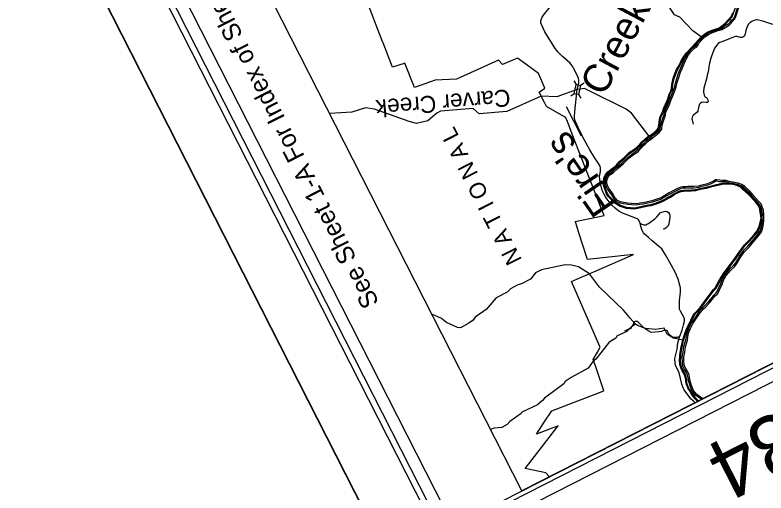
# Model space of a CAD drawing. Extents: x 558484 to 564063, y 513718 to 518374.
# Drawn here: x 559153.7 to 559464.9, y 514651.4 to 514849.4 of the extents above; entities that cross this region are included whole.
import ezdxf

# ---------------------------------------------------------------- set-up
doc = ezdxf.new("R2010")
doc.units = 0
for name, color, linetype in [('Default', 7, 'Continuous'), ('Scratch_Level_3', 7, 'Continuous'), ('Sheet Cutting Line CELL', 7, 'Continuous'), ('Sheet Plot Border Inside CELL', 7, 'Continuous'), ('Sheet Plot Border Outside CELL', 7, 'Continuous'), ('Sheet Title CELL', 7, 'Continuous')]:
    doc.layers.add(name, color=color, linetype=linetype)

msp = doc.modelspace()

# ---------------------------------------------------------------- linework, layer by layer
at = {"layer": 'Default'}
for p, q in [((559385.31, 514822.07), (559386.27, 514820.59)), ((559389.52, 514821.17), (559388.04, 514820.21)), ((559385.49, 514816.8), (559384.01, 514815.83)), ((559387.22, 514816.43), (559388.18, 514814.94)), ((559388.46, 514799.17), (559382.26, 514811.36))]:
    msp.add_line(p, q, dxfattribs=at)
for points in [[(559363.74, 514652.18), (559165.18, 515042.19), (559493.11, 515209.15), (559691.68, 514819.14)], [(559363.74, 514652.18), (559165.18, 515042.19), (559493.11, 515209.15), (559691.68, 514819.14)], [(559388.04, 514820.21), (559387.23, 514816.42), (559385.46, 514816.8), (559386.27, 514820.59)]]:
    msp.add_lwpolyline(points, close=True, dxfattribs=at)
for points in [[(559438.04, 514840.42), (559434.6, 514842.86), (559429.22, 514848.57), (559426.93, 514849.54), (559424.22, 514853.6), (559420.44, 514853.19), (559418.74, 514853.42), (559413.82, 514853.95), (559411.59, 514857.68), (559408.83, 514859.59), (559405, 514861.93), (559403.35, 514863.12), (559402.06, 514865.88), (559401.2, 514868.14), (559400.51, 514869.94), (559399.78, 514872.78), (559399.14, 514873.55), (559398.35, 514873.79)], [(559451.1, 514846.95), (559451.84, 514847.68), (559452.31, 514848.44), (559452.95, 514850.51), (559453.48, 514852.3), (559453.83, 514854.3), (559454.33, 514855.2), (559454.71, 514857.19), (559455.02, 514858.28), (559455.72, 514859.28), (559456.81, 514860.08), (559458.61, 514860.74), (559459.49, 514860.8), (559460.86, 514861.37), (559463.2, 514862.23), (559464.58, 514863), (559465.98, 514863.72)], [(559375.24, 514658.04), (559373.64, 514659.77), (559365.12, 514661.5), (559366.59, 514663.4), (559378.81, 514679.13), (559369.79, 514675.7), (559373.06, 514680.64), (559376.23, 514685.44), (559377.93, 514686.09), (559397.75, 514693.63), (559394.35, 514703.64), (559393.35, 514706.61), (559395.04, 514709.67), (559396.19, 514711.74), (559396.03, 514712.1), (559384.27, 514738.97), (559389.31, 514741.15), (559390.11, 514741.5), (559392.93, 514742.72), (559393.58, 514743), (559410.05, 514750.13), (559390.95, 514748.16), (559390.92, 514748.16), (559387.28, 514759.52), (559386.52, 514761.87), (559386.07, 514763.3), (559385.89, 514763.86), (559391.87, 514765.06), (559397.88, 514766.27), (559396.66, 514769.37), (559384.65, 514800), (559382.61, 514805.22), (559381.97, 514806.86), (559381.11, 514807.36), (559373.89, 514811.55), (559373.12, 514813.11), (559370.96, 514817.42), (559373.22, 514819.07), (559371.55, 514823.02), (559370.66, 514825.14), (559365.37, 514829.01), (559361.91, 514831.54), (559355.7, 514828.93), (559354.08, 514830.68), (559342.4, 514825.46), (559336.63, 514822.88), (559327.78, 514822.41), (559319.25, 514819.31), (559315.29, 514829.44), (559314.98, 514829.34), (559310.11, 514827.77), (559306.25, 514837.85), (559306.18, 514838.03), (559298.85, 514857.17)], [(559438.33, 514840.14), (559439.81, 514841.31), (559440.98, 514842.11), (559443.09, 514842.96), (559445.67, 514843.83), (559446.87, 514844.66), (559448.27, 514845.79), (559449.57, 514847.14), (559450.87, 514848.67), (559451.5, 514850.13), (559452.25, 514852.5), (559452.8, 514854.03), (559453.04, 514855.01), (559453.11, 514855.8), (559453.15, 514855.94)], [(559386.72, 514818.5), (559386.82, 514819.3), (559387.3, 514821.28), (559387.31, 514822.37), (559387.18, 514823.15), (559386.88, 514823.98), (559385.17, 514827.35), (559384.56, 514828.37), (559383.71, 514829.47), (559382.69, 514830.48), (559380.55, 514832.25), (559378.78, 514834), (559378.19, 514834.7), (559377.57, 514835.56), (559376.66, 514836.97), (559374.32, 514840.59), (559373.29, 514842.45), (559372.55, 514844.02), (559371.84, 514845.43), (559371.66, 514846.19), (559371.66, 514847.03), (559371.87, 514847.88), (559372.18, 514848.5), (559372.71, 514849.31), (559375.62, 514852.89)], [(559450.62, 514847.29), (559451.52, 514847.94), (559451.93, 514848.62), (559452.56, 514850.63), (559453.07, 514852.39), (559453.43, 514854.44), (559453.72, 514854.86)], [(559438.04, 514840.42), (559439.6, 514841.6), (559440.81, 514842.43), (559442.96, 514843.3), (559445.51, 514844.16), (559446.65, 514844.95), (559448.03, 514846.05), (559449.3, 514847.38), (559450.56, 514848.87), (559451.16, 514850.26)], [(559425.7, 514816.19), (559426.74, 514818.62), (559427.08, 514819.85), (559427.4, 514821.23), (559428.44, 514824.49), (559428.96, 514826), (559429.63, 514827.52), (559431.16, 514831.1), (559432.36, 514833.21), (559433.31, 514834.56), (559434.96, 514836.2), (559435.72, 514836.61), (559436.12, 514837.06), (559436.74, 514838.23), (559437.99, 514839.41), (559439.32, 514840.58), (559440.81, 514841.83), (559442.15, 514842.46), (559444.52, 514843.15), (559446.41, 514843.71), (559447.89, 514844.88), (559449.35, 514845.75), (559450.04, 514846.46), (559450.62, 514847.29)], [(559426.25, 514815.97), (559427.29, 514818.42), (559427.65, 514819.71), (559427.97, 514821.07), (559429, 514824.3), (559429.51, 514825.79), (559430.18, 514827.29), (559431.69, 514830.84), (559432.86, 514832.89), (559433.76, 514834.18), (559435.31, 514835.72), (559436.09, 514836.14), (559436.6, 514836.73), (559437.23, 514837.89), (559438.34, 514839.12), (559439.58, 514840.31), (559441.12, 514841.33), (559442.46, 514842.08), (559444.74, 514842.82), (559446.64, 514843.38), (559448.2, 514844.37), (559449.72, 514845.28), (559450.5, 514846.08), (559451.1, 514846.95)], [(559467.7, 514845.52), (559463.53, 514846.91), (559461.25, 514847.46), (559460.92, 514847.45), (559459.88, 514847.16), (559458.97, 514846.77), (559458.28, 514846.29), (559457.57, 514845.48), (559456.92, 514844.29), (559456.56, 514843.05), (559456.28, 514841.58), (559455.96, 514840.81), (559455.72, 514840.5), (559455.27, 514840.2), (559454.84, 514840.07), (559454.4, 514840.09), (559452.85, 514840.51), (559452.28, 514840.54), (559451.42, 514840.23), (559449.75, 514839.55), (559447.29, 514838.6), (559445.82, 514837.99), (559445.14, 514837.54), (559444.46, 514836.84), (559443.77, 514835.83), (559442.87, 514833.94), (559442.05, 514831.58), (559441.4, 514828.97), (559441.02, 514826.76), (559440.93, 514825.81), (559440.6, 514824.48), (559440.34, 514823.58), (559439.18, 514819.1), (559438.98, 514817.89), (559438.98, 514817.41), (559439.34, 514816.17), (559439.43, 514815.9), (559439.62, 514815.65), (559440.41, 514815.05), (559440.87, 514814.24), (559440.98, 514813.73), (559440.86, 514813.35), (559440.61, 514813.11), (559440.17, 514813.12), (559438.88, 514813.3), (559438.18, 514813.15), (559437.7, 514812.85), (559437.32, 514812.47), (559436.89, 514811.09), (559436.75, 514810.36), (559436.69, 514809.87), (559436.6, 514809.54), (559436.39, 514809.22), (559434.9, 514807.93), (559434.51, 514807.54), (559434.28, 514806.93), (559434.22, 514806.46), (559434.29, 514806.04), (559434.74, 514804.14)], [(559416.42, 514799.32), (559417.14, 514799.83), (559418.55, 514800.74), (559419.84, 514802.02), (559420.22, 514802.54), (559420.32, 514803.1), (559420.66, 514804.94), (559420.8, 514806.24), (559421.12, 514807.32), (559421.83, 514808.87), (559422.62, 514810.99), (559423.27, 514812.48), (559424.27, 514814.69), (559424.75, 514816.56), (559425.42, 514818.02), (559425.71, 514818.91), (559425.93, 514820.62), (559426.51, 514823.24), (559427, 514824.77), (559427.88, 514826.82), (559429.01, 514828.76), (559429.66, 514830.18), (559430.87, 514832.16), (559431.89, 514833.58), (559434.2, 514836.1), (559435.49, 514837.67), (559436.76, 514839.05), (559438.04, 514840.42)], [(559416.67, 514799.01), (559417.37, 514799.5), (559418.8, 514800.43), (559420.15, 514801.76), (559420.6, 514802.38), (559420.71, 514803.03), (559421.05, 514804.88), (559421.2, 514806.16), (559421.5, 514807.18), (559422.2, 514808.71), (559423, 514810.84), (559423.64, 514812.31), (559424.65, 514814.55), (559425.13, 514816.43), (559425.79, 514817.88), (559426.1, 514818.82), (559426.33, 514820.55), (559426.9, 514823.14), (559427.37, 514824.63), (559428.23, 514826.64), (559429.36, 514828.57), (559430.02, 514829.99), (559431.2, 514831.94), (559432.2, 514833.32), (559434.5, 514835.84), (559435.79, 514837.41), (559437.05, 514838.78), (559438.33, 514840.14)], [(559416.42, 514799.32), (559409.17, 514808.74), (559406.97, 514810.46), (559391.94, 514817.79), (559389.66, 514818.93), (559386.72, 514818.5), (559378.18, 514815.49), (559371.74, 514815.74), (559357.47, 514809.47), (559346.06, 514808.47), (559343.63, 514810.66), (559330.05, 514809.55), (559328.57, 514808.74), (559324.78, 514805.61), (559320.13, 514804.52), (559316.99, 514805.25), (559309.31, 514808.07), (559302.67, 514810.37), (559299.01, 514811), (559293.25, 514809.13), (559284.12, 514808.57)], [(559412.74, 514763.1), (559412.66, 514763.5), (559412.35, 514764.1), (559412.13, 514764.52), (559411.73, 514764.9), (559411.28, 514765.14), (559405.11, 514767.47), (559404.18, 514767.99), (559403.33, 514768.54), (559402.45, 514769.33), (559401.04, 514770.67), (559400, 514771.86), (559399.32, 514772.64), (559398.35, 514774.13), (559397.85, 514774.97), (559397.33, 514776.11), (559396.9, 514777.25), (559396.13, 514780.12), (559395.92, 514782.51), (559396.27, 514784.52), (559396.33, 514785.92), (559396.17, 514786.81), (559395.55, 514787.92), (559393.85, 514790.42), (559391.87, 514793.59), (559389.65, 514797.61), (559387.8, 514801.35), (559385.88, 514805.57), (559385.6, 514806.52), (559385.52, 514807.27), (559385.64, 514809.44), (559386.72, 514818.5)], [(559462.64, 514770.4), (559462.42, 514770.79), (559461.43, 514771.85), (559459.06, 514774.53), (559457.87, 514775.82), (559455.72, 514777.92), (559454.66, 514778.69), (559453.24, 514779.16), (559450.89, 514779.6), (559449.46, 514779.83), (559448.31, 514780.25), (559446.93, 514780.27), (559445.69, 514780.35), (559444.46, 514780.53), (559444.17, 514780.53), (559443.41, 514780.11), (559442.12, 514779.42), (559440.83, 514778.96), (559437.89, 514778.17), (559437.09, 514777.93), (559435.05, 514777.73), (559432.58, 514777.72), (559431.62, 514777.6), (559430.42, 514777.67), (559429.77, 514777.54), (559428.45, 514777.03), (559427.2, 514776.31), (559425.11, 514775.17), (559422.64, 514773.74), (559421.28, 514772.98), (559419.87, 514772.52), (559417.73, 514771.8), (559414.09, 514771.02), (559412.67, 514770.87), (559411.42, 514770.64), (559409.16, 514770.73), (559407.46, 514770.87), (559404.44, 514771.41), (559403.08, 514772.05), (559401.82, 514773.46), (559401.02, 514774.92), (559399.3, 514777.29), (559398.78, 514778.2), (559398.42, 514779.58), (559398.37, 514780.89), (559398.99, 514782.64), (559399.82, 514783.62), (559401.21, 514784.49), (559403.23, 514786.37), (559405.29, 514788.22), (559407.74, 514790.48), (559409.54, 514791.94), (559410.72, 514792.66), (559411.59, 514793.43), (559412.32, 514794.28), (559412.74, 514794.61), (559413.75, 514795.72), (559414.51, 514796.5), (559415.65, 514797.59), (559416.55, 514798.16), (559417.38, 514798.8), (559418.2, 514799.57), (559419.3, 514800.39), (559420.32, 514801.25), (559421.12, 514802.35), (559421.35, 514803.82), (559421.69, 514805.34), (559422.2, 514806.65), (559422.7, 514808.06), (559422.89, 514809.28), (559423.43, 514810.64), (559424.09, 514811.85), (559424.49, 514812.99), (559424.9, 514814.23), (559425.7, 514816.19)], [(559463.23, 514770.55), (559462.9, 514771.15), (559461.86, 514772.25), (559459.5, 514774.92), (559458.3, 514776.23), (559456.1, 514778.37), (559454.94, 514779.22), (559453.39, 514779.73), (559450.99, 514780.18), (559449.61, 514780.4), (559448.42, 514780.83), (559446.95, 514780.86), (559445.75, 514780.93), (559444.5, 514781.12), (559444.02, 514781.12), (559443.12, 514780.63), (559441.88, 514779.96), (559440.65, 514779.52), (559437.73, 514778.74), (559436.98, 514778.51), (559435.02, 514778.32), (559432.54, 514778.31), (559431.6, 514778.19), (559430.38, 514778.26), (559429.61, 514778.11), (559428.19, 514777.56), (559426.91, 514776.82), (559424.82, 514775.69), (559422.35, 514774.26), (559421.04, 514773.52), (559419.68, 514773.08), (559417.57, 514772.37), (559414, 514771.6), (559412.59, 514771.46), (559411.38, 514771.23), (559409.2, 514771.32), (559407.54, 514771.45), (559404.62, 514771.98), (559403.44, 514772.54), (559402.3, 514773.8), (559401.52, 514775.24), (559399.8, 514777.61), (559399.34, 514778.43), (559399.01, 514779.66), (559398.96, 514780.8), (559399.51, 514782.34), (559400.21, 514783.16), (559401.57, 514784.02), (559403.62, 514785.94), (559405.69, 514787.78), (559408.13, 514790.04), (559409.88, 514791.45), (559411.07, 514792.19), (559412.02, 514793.02), (559412.73, 514793.85), (559413.14, 514794.17), (559414.18, 514795.31), (559414.93, 514796.08), (559416.02, 514797.12), (559416.89, 514797.67), (559417.77, 514798.35), (559418.58, 514799.11), (559419.67, 514799.93), (559420.75, 514800.85), (559421.68, 514802.11), (559421.93, 514803.71), (559422.25, 514805.17), (559422.75, 514806.44), (559423.27, 514807.92), (559423.46, 514809.12), (559423.96, 514810.39), (559424.63, 514811.61), (559425.05, 514812.8), (559425.46, 514814.03), (559426.25, 514815.97)], [(559404.5, 514770.13), (559403.34, 514770.8), (559401.98, 514771.6), (559401, 514772.64), (559399.66, 514774.1), (559398.88, 514775.23), (559398.37, 514776.6), (559397.75, 514778.41), (559397.41, 514779.58), (559397.67, 514781.78), (559398.28, 514783.1), (559398.76, 514783.8), (559399.41, 514784.44), (559400.82, 514785.48), (559402.65, 514786.86), (559404.23, 514788.69), (559406.29, 514790.54), (559408.4, 514792.53), (559410.14, 514793.69), (559411.3, 514794.58), (559412.74, 514796.03), (559413.49, 514796.84), (559414.68, 514797.96), (559416.42, 514799.32)], [(559404.64, 514770.51), (559403.55, 514771.15), (559402.23, 514771.92), (559401.29, 514772.91), (559399.97, 514774.35), (559399.24, 514775.42), (559398.75, 514776.74), (559398.13, 514778.53), (559397.82, 514779.62), (559398.06, 514781.67), (559398.63, 514782.9), (559399.07, 514783.54), (559399.67, 514784.13), (559401.06, 514785.15), (559402.93, 514786.57), (559404.52, 514788.4), (559406.56, 514790.25), (559408.65, 514792.21), (559410.37, 514793.37), (559411.57, 514794.28), (559413.03, 514795.75), (559413.78, 514796.56), (559414.94, 514797.66), (559416.67, 514799.01)], [(559430.38, 514714.64), (559431.33, 514717.62), (559432.38, 514720.17), (559433.73, 514722.98), (559434.79, 514724.97), (559435.45, 514725.92), (559437.37, 514727.97), (559438.69, 514729.7), (559440.96, 514732.74), (559443.11, 514735.68), (559443.89, 514736.42), (559445.67, 514739.66), (559447.55, 514742.68), (559449.27, 514744.88), (559451.15, 514747.48), (559452.16, 514748.79), (559453.77, 514751.19), (559455.99, 514754.14), (559457.74, 514756.02), (559460.02, 514758.47), (559461.27, 514759.92), (559462.13, 514761.92), (559462.67, 514764.19), (559462.89, 514765.24), (559462.5, 514767.73), (559462.16, 514769.61), (559461.58, 514770.77), (559460.38, 514772.11), (559457.69, 514775.09), (559455.33, 514777.14), (559454.3, 514778.09), (559452.89, 514778.71), (559451.2, 514779.14), (559449.3, 514779.3), (559446.78, 514779.18), (559444.41, 514778.68), (559441.88, 514778.03), (559440.09, 514777.59), (559437.64, 514777.05), (559435.69, 514776.61), (559434.09, 514776.43), (559430.67, 514776.3), (559429.61, 514776.14), (559428.83, 514775.92), (559427.3, 514775.11), (559425.57, 514773.99), (559424.65, 514773.53), (559423.62, 514772.9), (559422.43, 514772.3), (559421.22, 514771.79), (559418.94, 514770.89), (559417.22, 514770.36), (559415.41, 514770.04), (559411.82, 514769.23), (559410.34, 514768.96), (559408.7, 514769.04), (559407.08, 514769.24), (559405.87, 514769.62), (559404.5, 514770.13)], [(559430.78, 514714.55), (559431.72, 514717.48), (559432.75, 514720), (559434.09, 514722.79), (559435.14, 514724.76), (559435.76, 514725.66), (559437.68, 514727.71), (559439.02, 514729.45), (559441.28, 514732.5), (559443.42, 514735.41), (559444.21, 514736.17), (559446.02, 514739.46), (559447.89, 514742.44), (559449.59, 514744.63), (559451.47, 514747.24), (559452.49, 514748.55), (559454.1, 514750.95), (559456.3, 514753.88), (559458.04, 514755.74), (559460.32, 514758.2), (559461.62, 514759.7), (559462.52, 514761.79), (559463.07, 514764.1), (559463.3, 514765.23), (559462.9, 514767.8), (559462.55, 514769.74), (559461.92, 514771), (559460.69, 514772.38), (559457.98, 514775.38), (559455.6, 514777.45), (559454.53, 514778.44), (559453.02, 514779.09), (559451.26, 514779.55), (559449.31, 514779.7), (559446.73, 514779.58), (559444.31, 514779.08), (559441.78, 514778.42), (559439.99, 514777.98), (559437.55, 514777.44), (559435.62, 514777.01), (559434.06, 514776.83), (559430.63, 514776.71), (559429.52, 514776.54), (559428.67, 514776.3), (559427.1, 514775.46), (559425.37, 514774.34), (559424.46, 514773.89), (559423.42, 514773.26), (559422.26, 514772.67), (559421.06, 514772.16), (559418.81, 514771.28), (559417.12, 514770.76), (559415.33, 514770.44), (559411.74, 514769.63), (559410.31, 514769.37), (559408.74, 514769.45), (559407.17, 514769.64), (559406.01, 514770.01), (559404.64, 514770.51)], [(559455.93, 514752.06), (559457.42, 514753.6), (559459.17, 514755.69), (559461.43, 514758.38), (559462.55, 514759.85), (559463.05, 514761.57), (559463.33, 514762.95), (559463.4, 514764.23), (559463.36, 514765.3), (559463.46, 514766.84), (559463.23, 514768.37), (559462.9, 514769.32), (559462.64, 514770.4)], [(559456.38, 514751.64), (559457.88, 514753.2), (559459.64, 514755.3), (559461.91, 514758), (559463.1, 514759.57), (559463.64, 514761.42), (559463.94, 514762.87), (559464.02, 514764.22), (559463.98, 514765.29), (559464.08, 514766.87), (559463.83, 514768.51), (559463.49, 514769.5), (559463.23, 514770.55)], [(559412.74, 514763.1), (559413.51, 514762.7), (559414.35, 514762.41), (559415.07, 514762.5), (559415.81, 514762.83), (559416.27, 514763.08), (559416.74, 514763.43), (559417.3, 514763.85), (559418.8, 514764.97), (559419.71, 514765.75), (559420.63, 514766.89), (559421.11, 514767.42), (559421.76, 514767.75), (559422.65, 514768.03), (559423.4, 514768.16), (559423.95, 514767.98), (559424.45, 514767.63), (559424.88, 514766.93), (559425.13, 514766.45), (559425.03, 514765.51), (559424.68, 514762.84), (559424.35, 514762.1), (559423.74, 514761.33), (559423.05, 514760.8), (559422.35, 514760.66)], [(559429.16, 514716.37), (559430.14, 514718.78), (559430.78, 514721.05), (559431.11, 514722.58), (559431.1, 514723.45), (559430.9, 514724.17), (559429.44, 514726.71), (559429.13, 514727.57), (559429.04, 514728.86), (559429.13, 514730.91), (559429.47, 514734.5), (559429.46, 514736.32), (559428.51, 514739.99), (559427.36, 514742.57), (559425.65, 514745.9), (559423.32, 514749.99), (559421.76, 514752.46), (559420.41, 514753.69), (559417.8, 514755.89), (559416.17, 514757.26), (559415.27, 514757.98), (559414.62, 514758.57), (559414.15, 514759.22), (559413.56, 514760.16), (559413.09, 514761.78), (559412.74, 514763.1)], [(559438.17, 514690.07), (559437.45, 514690.58), (559435.79, 514691.75), (559434.35, 514693.55), (559433.48, 514695.74), (559432.87, 514697.5), (559432.63, 514699.05), (559432.44, 514700.19), (559431.97, 514701.21), (559431.15, 514702.48), (559430.5, 514703.92), (559430.31, 514705.68), (559430.23, 514707.61), (559430.61, 514709.83), (559430.93, 514712.03), (559431.48, 514713.86), (559431.72, 514714.87), (559431.96, 514716.07), (559432.21, 514717.77), (559432.99, 514719.52), (559434.24, 514721.99), (559435.93, 514724.54), (559437.51, 514726.92), (559438.56, 514728.05), (559439.49, 514728.92), (559441.09, 514730.61), (559442.69, 514732.55), (559443.35, 514733.39), (559444.27, 514734.27), (559444.95, 514735.38), (559445.5, 514736.81), (559446.18, 514738.02), (559446.79, 514739.82), (559447.95, 514741.87), (559449.71, 514743.95), (559451.5, 514745.6), (559452.35, 514746.79), (559453.18, 514748.11), (559453.97, 514749.48), (559455.44, 514751.53), (559455.93, 514752.06)], [(559438.78, 514690.39), (559437.8, 514691.08), (559436.21, 514692.21), (559434.88, 514693.86), (559434.06, 514695.95), (559433.46, 514697.64), (559433.24, 514699.15), (559433.03, 514700.37), (559432.51, 514701.51), (559431.69, 514702.77), (559431.1, 514704.09), (559430.92, 514705.73), (559430.85, 514707.57), (559431.21, 514709.74), (559431.53, 514711.9), (559432.07, 514713.7), (559432.32, 514714.74), (559432.57, 514715.97), (559432.8, 514717.6), (559433.55, 514719.26), (559434.77, 514721.68), (559436.44, 514724.2), (559437.99, 514726.54), (559439, 514727.62), (559439.92, 514728.48), (559441.55, 514730.2), (559443.17, 514732.17), (559443.8, 514732.98), (559444.75, 514733.88), (559445.5, 514735.11), (559446.06, 514736.55), (559446.74, 514737.77), (559447.35, 514739.57), (559448.46, 514741.52), (559450.15, 514743.52), (559451.96, 514745.2), (559452.86, 514746.45), (559453.71, 514747.79), (559454.49, 514749.15), (559455.91, 514751.14), (559456.38, 514751.64)], [(559408.65, 514723.84), (559405.93, 514727.09), (559395.87, 514736.69), (559391.72, 514742.1), (559387.26, 514745.09), (559384.36, 514745.79), (559381.65, 514745.85), (559371.85, 514743.87), (559369.38, 514742.62), (559367.31, 514739.97), (559363.63, 514738.04), (559362.07, 514737.62), (559359, 514735.96), (559357.61, 514734.62), (559353.1, 514732.16), (559348.95, 514727.44), (559344.46, 514724.14), (559343.53, 514723), (559341.84, 514721.68), (559338.26, 514719.78), (559337.04, 514719.94), (559332.54, 514722.06), (559330.4, 514723.67), (559326.42, 514725.48)], [(559429.16, 514716.37), (559428.25, 514715.83), (559427.69, 514715.77), (559426.72, 514715.79), (559426.13, 514715.9), (559425.7, 514716.16), (559425.05, 514716.77), (559424.61, 514717.32), (559424.32, 514717.91), (559424.03, 514718.36), (559423.74, 514718.65), (559423.43, 514718.73), (559422.41, 514718.67), (559421.59, 514718.33), (559420.52, 514718.11), (559418.91, 514718.03), (559417.33, 514717.92), (559416.33, 514718.35), (559414.85, 514719.39), (559413.48, 514720.6), (559411.96, 514722.18), (559411.58, 514722.36), (559411.15, 514722.45), (559410.67, 514722.41), (559410.2, 514722.11), (559410.04, 514721.79), (559410.04, 514721.44), (559409.95, 514721.25), (559409.79, 514721.03), (559409.33, 514720.3), (559408.61, 514719.61), (559407.89, 514719.12), (559407.41, 514718.9), (559406.32, 514718.37)], [(559410.79, 514721.28), (559408.65, 514723.84)], [(559410.79, 514721.28), (559409.09, 514720.09), (559408.98, 514719.61), (559407.73, 514718.91), (559407.52, 514718.39), (559405.48, 514717.47)], [(559430.38, 514714.64), (559426.41, 514715.46), (559423.92, 514717.2), (559422.68, 514719.64), (559419.11, 514719.03), (559415.02, 514719.47), (559411.6, 514720.79), (559410.79, 514721.28)], [(559405.48, 514717.47), (559403.27, 514716.47), (559402.71, 514715.51), (559399.89, 514713.81), (559399.53, 514713.36)], [(559435.6, 514688.77), (559434.85, 514689.36), (559433.93, 514690.28), (559431.71, 514693.08), (559430.98, 514694.15), (559430.6, 514694.91), (559430.06, 514696.45), (559428.98, 514701.2), (559427.44, 514704.3), (559427.26, 514704.97), (559427.09, 514707.08), (559427.74, 514709.32), (559428.06, 514710.94), (559428.38, 514713.6), (559429.16, 514716.37)], [(559399.53, 514713.36), (559394.36, 514706.76), (559393.26, 514705.98), (559391.2, 514703.06), (559384.19, 514699.2), (559381.71, 514697.51), (559381.11, 514696.52), (559373.08, 514690.63), (559372.24, 514689.68), (559370.19, 514687.91), (559363.7, 514684.84), (559363.5, 514684.33), (559358.72, 514681.03), (559357.61, 514679.68), (559355.43, 514678.42), (559352.31, 514678.15), (559350.8, 514677.6)], [(559432.07, 514696.01), (559431.75, 514697.23), (559431.67, 514698.33), (559431.29, 514699.84), (559430.71, 514701.13), (559430.2, 514701.99), (559429.61, 514703.17), (559429.23, 514704.61), (559429.09, 514706.27), (559429.17, 514708.03), (559429.29, 514709.56), (559429.77, 514711.86), (559430.38, 514714.64)], [(559432.45, 514696.17), (559432.16, 514697.3), (559432.08, 514698.4), (559431.68, 514699.97), (559431.07, 514701.32), (559430.56, 514702.19), (559429.99, 514703.32), (559429.63, 514704.68), (559429.49, 514706.28), (559429.58, 514708), (559429.7, 514709.51), (559430.17, 514711.78), (559430.78, 514714.55)], [(559436.66, 514689.31), (559435.55, 514690.36), (559434.22, 514692.05), (559432.87, 514694.21), (559432.49, 514694.96), (559432.07, 514696.01)], [(559437.09, 514689.53), (559436.94, 514689.6), (559435.86, 514690.64), (559434.55, 514692.29), (559433.23, 514694.41), (559432.86, 514695.13), (559432.45, 514696.17)]]:
    msp.add_lwpolyline(points, dxfattribs=at)
at = {"layer": 'Scratch_Level_3'}
msp.add_line((559481.39, 514712.08), (559211.34, 514574.59), dxfattribs=at)
at = {"layer": 'Sheet Cutting Line CELL'}
msp.add_line((559410.15, 514424.68), (558646.11, 515925.37), dxfattribs=at)
at = {"layer": 'Sheet Plot Border Inside CELL'}
msp.add_lwpolyline([(560364.51, 514925.16), (559608.41, 516410.26), (558668.16, 515931.55), (559424.26, 514446.45)], close=True, dxfattribs=at)
at = {"layer": 'Sheet Plot Border Outside CELL'}
msp.add_lwpolyline([(558646.11, 515925.37), (559410.15, 514424.68), (560390.41, 514923.75), (559626.36, 516424.45)], close=True, dxfattribs=at)
at = {"layer": 'Sheet Title CELL'}
for p, q in [((560256.31, 515098.98), (559347.33, 514636.2)), ((560089.18, 515019.5), (559345.07, 514640.66))]:
    msp.add_line(p, q, dxfattribs=at)
for points in [[(558680.63, 515912.67), (559352.12, 514593.74)], [(558687.36, 515910.47), (559331.62, 514645.05)]]:
    msp.add_lwpolyline(points, dxfattribs=at)

# ---------------------------------------------------------------- texts
at = {"layer": 'Default'}
for s, height, rotation, p in [('Creek', 11.719, 62.0399, (559397.72, 514815.34)), ('Carver Creek', 7.0312, 184.674, (559358.71, 514818.7)), ('N A T I O N A L', 6.7187, 116.9819, (559363.89, 514747.97)), ("Fire's", 11.719, 124.5153, (559403.63, 514771.07))]:
    msp.add_text(s, height=height, rotation=rotation, dxfattribs=at).set_placement(p)
at = {"layer": 'Sheet Title CELL'}
for s, height, rotation, p in [('See Sheet 1-A For Index of Sheets', 7.5, 116.9819, (559304.76, 514730.22)), ('B-4734  ', 25, 206.9819, (559534.25, 514718.59))]:
    msp.add_text(s, height=height, rotation=rotation, dxfattribs=at).set_placement(p)

doc.saveas('drawing.dxf')
